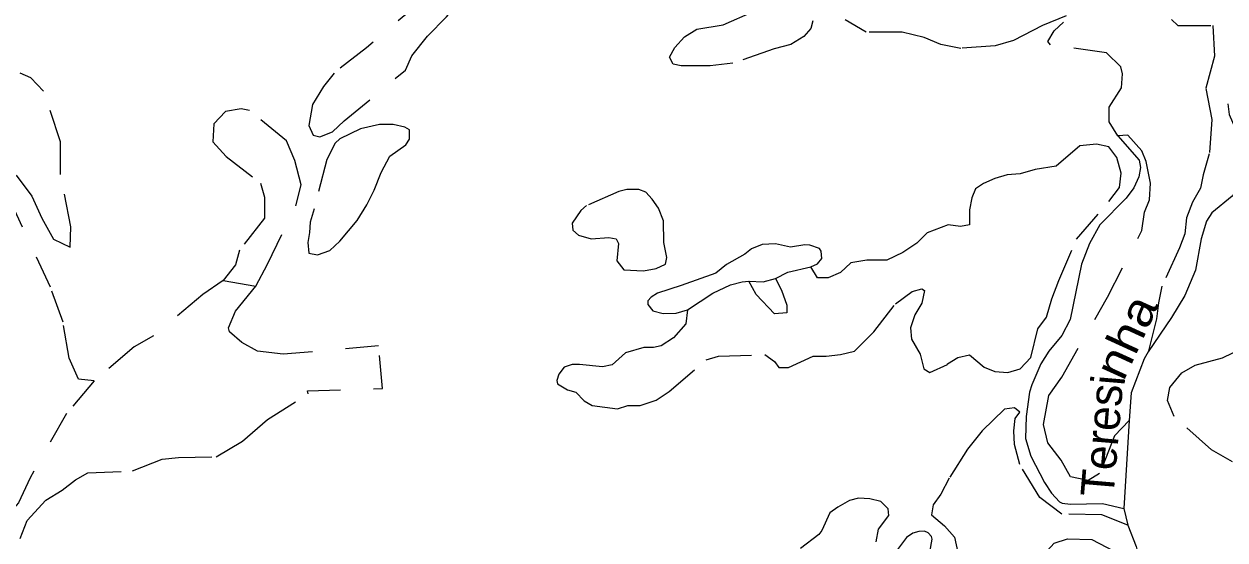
# Model space of a CAD drawing. Extents: x 344.9 to 371, y 7566.4 to 7594.3.
# Drawn here: x 363.484 to 367.111, y 7578.737 to 7580.297 of the extents above; entities that cross this region are included whole.
import ezdxf
from ezdxf.enums import TextEntityAlignment as Align

# ---------------------------------------------------------------- set-up
doc = ezdxf.new("R2010")
doc.units = 0
doc.header["$LTSCALE"] = 0.04
doc.linetypes.add('LONG_DASHED', pattern=[7.5, 6, -1.5])
doc.linetypes.add('SHORT_DASHED', pattern=[2.7, 1.5, -1.2])
for name, color, linetype, lineweight in [('17', 7, 'SHORT_DASHED', 13), ('21', 7, 'SHORT_DASHED', 13), ('3', 7, 'LONG_DASHED', 25), ('7', 7, 'Continuous', 25)]:
    doc.layers.add(name, color=color, linetype=linetype, lineweight=lineweight)
doc.layers.add('61', color=7, linetype='Continuous')

msp = doc.modelspace()

# ---------------------------------------------------------------- linework, layer by layer
at = {"layer": '17'}
msp.add_line((364.0854, 7579.5211), (364.1845, 7579.5046), dxfattribs=at)
msp.add_lwpolyline([(363.6963, 7579.2182), (363.6124, 7579.1193), (363.503, 7578.9253), (363.4679, 7578.8489), (363.4251, 7578.8008)], dxfattribs=at)
at = {"layer": '21'}
for p, q in [((365.8806, 7579.5294), (365.8599, 7579.5632)), ((364.5551, 7579.3236), (364.267, 7579.2982))]:
    msp.add_line(p, q, dxfattribs=at)
for points in [[(364.7411, 7580.4042), (364.6905, 7580.3713), (364.5183, 7580.2244), (364.4208, 7580.1485), (364.3891, 7580.1079), (364.3549, 7580.0535), (364.3448, 7579.9902), (364.3575, 7579.9611), (364.3777, 7579.956), (364.4157, 7579.9712), (364.4512, 7580.0041), (364.636, 7580.1573), (364.655, 7580.2004), (364.7031, 7580.2599), (364.7601, 7580.3181), (364.8222, 7580.3916), (364.831, 7580.4118), (364.826, 7580.4321), (364.8146, 7580.4429), (364.7943, 7580.4454)], [(364.5786, 7579.9928), (364.5582, 7579.9928), (364.5003, 7579.9799), (364.438, 7579.9499), (364.4241, 7579.937), (364.3983, 7579.8876), (364.3608, 7579.7385), (364.3479, 7579.6977), (364.3468, 7579.6666), (364.3415, 7579.6365), (364.3447, 7579.6044), (364.3704, 7579.599), (364.408, 7579.6119), (364.438, 7579.6408), (364.4906, 7579.7031), (364.5196, 7579.7503), (364.5421, 7579.7943), (364.5625, 7579.8479), (364.5893, 7579.8973), (364.6376, 7579.9316), (364.6484, 7579.9488), (364.6484, 7579.9767), (364.6344, 7579.9853), (364.599, 7579.9928)], [(365.4, 7579.7398), (365.3815, 7579.7676), (365.3618, 7579.7885), (365.3409, 7579.7966), (365.305, 7579.7966), (365.2806, 7579.7908), (365.1833, 7579.7479), (365.1659, 7579.7328), (365.1392, 7579.6946), (365.1415, 7579.6737), (365.1589, 7579.6586), (365.1972, 7579.6471), (365.2505, 7579.6517), (365.2725, 7579.6471), (365.2795, 7579.6331), (365.2748, 7579.581), (365.2957, 7579.5532), (365.3548, 7579.5508), (365.3931, 7579.5578), (365.4209, 7579.5706), (365.4255, 7579.5914), (365.4162, 7579.6366), (365.4151, 7579.7015)]]:
    msp.add_lwpolyline(points, close=True, dxfattribs=at)
for points in [[(365.8659, 7580.3067), (365.8606, 7580.2828), (365.8394, 7580.259), (365.7996, 7580.2351), (365.7493, 7580.2219), (365.6247, 7580.1782), (365.5558, 7580.1702), (365.4684, 7580.1702), (365.4445, 7580.1755), (365.4339, 7580.1967), (365.4498, 7580.2259), (365.479, 7580.2577), (365.5161, 7580.2815), (365.5956, 7580.2948), (365.7996, 7580.3848)], [(366.6317, 7580.3212), (366.5601, 7580.2921), (366.4727, 7580.2471), (366.417, 7580.2312), (366.3137, 7580.2232), (366.2528, 7580.2351), (366.2024, 7580.2563), (366.1362, 7580.2722), (366.0275, 7580.2722), (365.9639, 7580.3093)], [(366.7876, 7579.9584), (366.7615, 7580.0007), (366.7615, 7580.0457), (366.7986, 7580.104), (366.8013, 7580.1464), (366.796, 7580.1676), (366.7536, 7580.21), (366.584, 7580.2338), (366.576, 7580.2444), (366.5946, 7580.2762), (366.6237, 7580.3027)], [(366.9496, 7580.3107), (366.9682, 7580.2921), (367.0742, 7580.2921), (367.0795, 7580.1994), (367.053, 7580.1014), (367.0715, 7580.0086), (367.0636, 7579.9039), (367.045, 7579.8404), (367.0371, 7579.8006), (367.0132, 7579.7582), (366.9947, 7579.7105), (366.9894, 7579.6628), (366.9735, 7579.6204), (366.9205, 7579.5039), (366.9099, 7579.4535), (366.9046, 7579.4058), (366.8791, 7579.3054)], [(363.4605, 7579.8395), (363.5076, 7579.7759), (363.5383, 7579.7098), (363.5737, 7579.6462), (363.6232, 7579.6226), (363.6255, 7579.6839), (363.5949, 7579.8419), (363.5949, 7579.9409), (363.543, 7580.0942), (363.5053, 7580.1343), (363.4723, 7580.1484)], [(364.1845, 7579.5046), (364.2198, 7579.5706), (364.3047, 7579.7475), (364.3212, 7579.8111), (364.3024, 7579.8842), (364.2764, 7579.9432), (364.1656, 7580.0352), (364.1397, 7580.0399), (364.0925, 7580.0328), (364.0571, 7579.9951), (364.0548, 7579.9408), (364.0949, 7579.896), (364.1986, 7579.8159), (364.2104, 7579.7734), (364.2104, 7579.7098), (364.1349, 7579.6131), (364.1232, 7579.5683), (364.0854, 7579.5211)], [(366.8211, 7579.0984), (366.7774, 7579.0521), (366.7324, 7578.9382), (366.6979, 7578.917), (366.6449, 7578.9276), (366.6158, 7578.9779), (366.576, 7579.0309), (366.5628, 7579.0865), (366.5787, 7579.174), (366.6184, 7579.2296), (366.7562, 7579.4707), (366.8596, 7579.6721), (366.8675, 7579.7277), (366.8834, 7579.7648), (366.8861, 7579.8152), (366.8728, 7579.8814), (366.8596, 7579.9132), (366.8172, 7579.9609), (366.7876, 7579.9584)], [(365.488, 7579.4328), (365.483, 7579.3903), (365.4459, 7579.3479), (365.4088, 7579.3241), (365.385, 7579.3188), (365.3558, 7579.3188), (365.3002, 7579.3029), (365.2608, 7579.266), (365.2308, 7579.2605), (365.1621, 7579.2676), (365.14, 7579.2672), (365.1155, 7579.2596), (365.0989, 7579.2383), (365.0934, 7579.2194), (365.0948, 7579.2086), (365.1252, 7579.191), (365.1506, 7579.1836), (365.1756, 7579.1572), (365.1995, 7579.1439), (365.2763, 7579.1333), (365.3081, 7579.1439), (365.3452, 7579.1439), (365.3929, 7579.1598), (365.4327, 7579.1863), (365.544, 7579.2817), (365.5811, 7579.2923), (365.7215, 7579.2976), (365.7506, 7579.2764), (365.7639, 7579.2579), (365.793, 7579.2579), (365.8672, 7579.2923), (365.907, 7579.2923), (365.9494, 7579.2976), (365.9918, 7579.3082), (366.0501, 7579.3665), (366.1163, 7579.4513), (366.1667, 7579.4884), (366.1958, 7579.4963), (366.2038, 7579.491), (366.1959, 7579.4526), (366.1747, 7579.4181), (366.1614, 7579.3784), (366.1641, 7579.3439), (366.1906, 7579.2989), (366.2012, 7579.2539), (366.2197, 7579.2433), (366.2727, 7579.2671), (366.2727, 7579.2698), (366.3045, 7579.2883), (366.3389, 7579.2963), (366.384, 7579.2592), (366.4158, 7579.2459), (366.4555, 7579.2433), (366.4926, 7579.2539), (366.5244, 7579.2883), (366.5456, 7579.3757), (366.5721, 7579.4102), (366.588, 7579.4658), (366.6092, 7579.5215), (366.6622, 7579.646), (366.7603, 7579.7599), (366.7921, 7579.8023), (366.7974, 7579.846), (366.7842, 7579.8937), (366.7603, 7579.9255), (366.7232, 7579.9335), (366.6729, 7579.9282), (366.6013, 7579.8672), (366.5377, 7579.8566), (366.4927, 7579.8434), (366.4529, 7579.8407), (366.4158, 7579.8301), (366.3814, 7579.8142), (366.3575, 7579.7983), (366.3469, 7579.7718), (366.339, 7579.7347), (366.339, 7579.6897), (366.3125, 7579.6844), (366.2754, 7579.6897), (366.2118, 7579.6658), (366.18, 7579.6341), (366.1376, 7579.6063), (366.0899, 7579.5824), (366.029, 7579.5824), (365.9813, 7579.5745), (365.9495, 7579.5453), (365.9124, 7579.5294), (365.8806, 7579.5294)], [(363.6963, 7579.2182), (363.6492, 7579.2229), (363.6209, 7579.2866), (363.602, 7579.395), (363.5643, 7579.5011), (363.4511, 7579.744)], [(364.0854, 7579.5211), (364.0241, 7579.4787), (363.8755, 7579.3537), (363.8166, 7579.3207), (363.6963, 7579.2182)], [(365.7533, 7579.5274), (365.7719, 7579.4923), (365.7878, 7579.4473), (365.7878, 7579.4235), (365.7507, 7579.4208), (365.6951, 7579.4791), (365.6735, 7579.5189)], [(364.267, 7579.2982), (364.1892, 7579.3077), (364.142, 7579.3336), (364.1043, 7579.3666), (364.1019, 7579.3784), (364.1232, 7579.4291), (364.1845, 7579.5046)], [(363.4723, 7578.7417), (363.4935, 7578.7959), (363.5501, 7578.8572), (363.5996, 7578.8879), (363.6397, 7578.9185), (363.6774, 7578.9397), (363.8118, 7578.9457), (363.9015, 7578.981), (363.951, 7578.9858), (364.0642, 7578.9881), (364.1443, 7579.0353), (364.2198, 7579.1013), (364.3424, 7579.1791), (364.3401, 7579.1874), (364.5663, 7579.1948), (364.5551, 7579.3236)], [(367.1336, 7578.9728), (367.0698, 7579.0097), (366.9574, 7579.1103), (366.9373, 7579.159), (366.944, 7579.1975), (366.9809, 7579.242), (367.0212, 7579.2654), (367.1034, 7579.2872), (367.1654, 7579.3174)], [(366.445, 7579.1322), (366.3778, 7579.0673), (366.3338, 7579.0117), (366.2782, 7578.9237), (366.2527, 7578.8751), (366.2296, 7578.8427), (366.225, 7578.8126), (366.2643, 7578.7802), (366.2944, 7578.7454), (366.313, 7578.6574), (366.3546, 7578.6111), (366.3987, 7578.5764), (366.4429, 7578.5893), (366.5098, 7578.6435), (366.5631, 7578.6922), (366.5955, 7578.7269), (366.6349, 7578.7408), (366.709, 7578.7385), (366.8016, 7578.6898), (366.8458, 7578.6816)], [(366.8172, 7578.7813), (366.7391, 7578.8126), (366.6187, 7578.8149), (366.5515, 7578.8658), (366.4913, 7578.9654), (366.4751, 7579.0256), (366.4728, 7579.0673), (366.4774, 7579.1044), (366.4913, 7579.1229), (366.4751, 7579.1368), (366.445, 7579.1322)], [(366.0573, 7578.7315), (366.0643, 7578.7693), (366.0954, 7578.8108), (366.0936, 7578.8309), (366.0716, 7578.8529), (366.0387, 7578.8611), (366.0039, 7578.8638), (365.9774, 7578.8565), (365.9417, 7578.8364), (365.9179, 7578.819), (365.8932, 7578.7659), (365.8841, 7578.7531), (365.8292, 7578.7111)]]:
    msp.add_lwpolyline(points, dxfattribs=at)
at = {"layer": '3'}
for points in [[(365.8599, 7579.5632), (365.8806, 7579.5719), (365.8931, 7579.5884), (365.8913, 7579.61), (365.8862, 7579.6184), (365.8571, 7579.628), (365.8419, 7579.6292), (365.7985, 7579.6218), (365.7538, 7579.6322), (365.7132, 7579.6299), (365.6809, 7579.6172), (365.661, 7579.601), (365.6052, 7579.5699), (365.5729, 7579.5435), (365.4686, 7579.5064)], [(365.7533, 7579.5274), (365.7911, 7579.5468), (365.8599, 7579.5632)], [(365.488, 7579.4328), (365.5646, 7579.4829), (365.6172, 7579.508), (365.6532, 7579.5173), (365.6735, 7579.5189)], [(365.6735, 7579.5189), (365.7164, 7579.5175), (365.7533, 7579.5274)], [(365.4686, 7579.5064), (365.3976, 7579.4831), (365.3782, 7579.4711), (365.368, 7579.4596), (365.368, 7579.449), (365.3828, 7579.4298), (365.4146, 7579.4219), (365.4538, 7579.4226), (365.488, 7579.4328)], [(366.0293, 7578.5907), (366.0303, 7578.5814), (366.0524, 7578.5632), (366.0695, 7578.5581), (366.0893, 7578.5581), (366.1391, 7578.5726), (366.1862, 7578.6017), (366.1987, 7578.6183), (366.2069, 7578.6356), (366.2148, 7578.6714), (366.2267, 7578.7391), (366.2249, 7578.7478), (366.2143, 7578.7585), (366.2037, 7578.7631), (366.1861, 7578.7621), (366.1686, 7578.7573), (366.1493, 7578.7444), (366.0819, 7578.6546)]]:
    msp.add_lwpolyline(points, dxfattribs=at)
at = {"layer": '7'}
for points in [[(367.1194, 7580.0558), (367.1236, 7580.0228), (367.1535, 7579.9533), (367.1687, 7579.9005), (367.1669, 7579.8303), (367.1604, 7579.8137), (367.1327, 7579.7766), (367.0714, 7579.7261), (367.0552, 7579.7007), (367.0391, 7579.6469), (367.0221, 7579.5523)], [(366.7876, 7579.9584), (366.8522, 7579.8848), (366.8553, 7579.8634), (366.8506, 7579.8348), (366.8355, 7579.8014), (366.8124, 7579.7704), (366.7334, 7579.6901), (366.7013, 7579.6331), (366.6775, 7579.5711), (366.6433, 7579.4035), (366.6187, 7579.3551), (366.579, 7579.3075), (366.5544, 7579.2694), (366.5274, 7579.2058), (366.521, 7579.1836), (366.5107, 7579.1106), (366.5083, 7579.0439), (366.525, 7578.9899), (366.5663, 7578.9104), (366.5873, 7578.8786)], [(367.0221, 7579.5523), (366.9893, 7579.4759), (366.9496, 7579.4097), (366.8791, 7579.3054)], [(366.8791, 7579.3054), (366.8666, 7579.2844), (366.8279, 7579.182), (366.8211, 7579.0984), (366.8057, 7578.8318), (366.8172, 7578.7813)], [(366.5873, 7578.8786), (366.6108, 7578.8524), (366.6188, 7578.8483), (366.6441, 7578.8453), (366.741, 7578.8477), (366.8057, 7578.8318)], [(366.8172, 7578.7813), (366.843, 7578.7176), (366.8467, 7578.7006), (366.8458, 7578.6816)]]:
    msp.add_lwpolyline(points, dxfattribs=at)

# ---------------------------------------------------------------- texts
at = {"layer": '61', "width": 1.15}
msp.add_text('nha', height=0.1, rotation=65.423, dxfattribs=at).set_placement((366.8578, 7579.3306), align=Align.CENTER)
at = {"layer": '61'}
for s, p in [('i', (366.8086, 7579.216)), ('Teres', (366.7883, 7579.034))]:
    msp.add_text(s, height=0.1, rotation=85.172, dxfattribs=at).set_placement(p, align=Align.CENTER)

doc.saveas('drawing.dxf')
